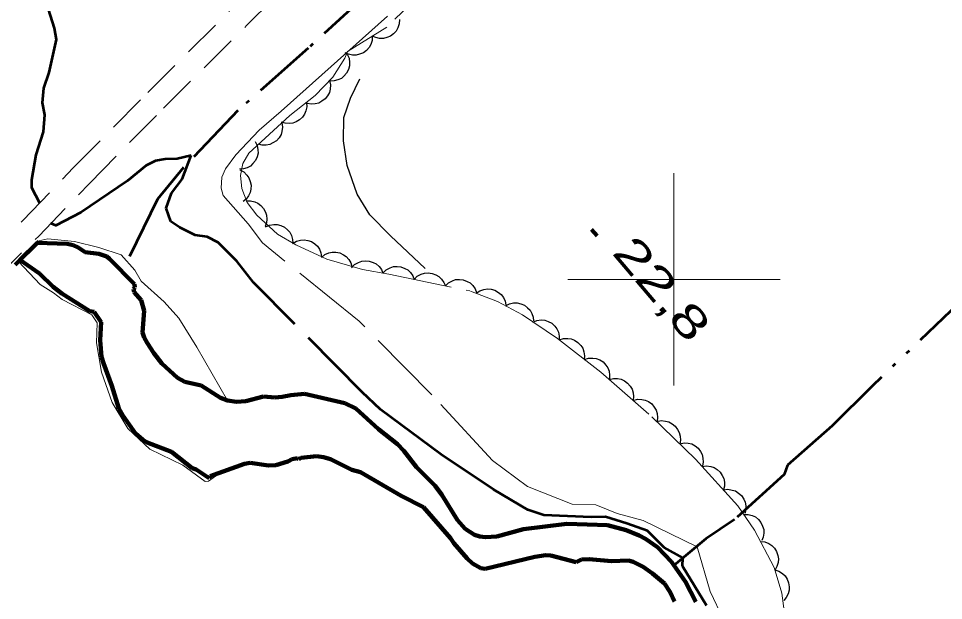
# Model space of a CAD drawing. Extents: x 386081 to 389416, y 5130568 to 5134082.
# Drawn here: x 387738.2 to 387825.4, y 5131569.7 to 5131624.6 of the extents above; entities that cross this region are included whole.
import ezdxf

# ---------------------------------------------------------------- set-up
doc = ezdxf.new("R2010")
doc.units = 0
doc.header["$LTSCALE"] = 1.2
for name, pattern in [('DASH_DOUBLE_DOT', [9.2, 5, -1.2, 0.3, -1.2, 0.3, -1.2]), ('DOT_DASHED', [7.7, 5, -1.2, 0.3, -1.2]), ('LONG_DASHED', [7.5, 6, -1.5]), ('MEDIUM_DASHED', [4.5, 3, -1.5])]:
    doc.linetypes.add(name, pattern=pattern)
for name, color, linetype, lineweight in [('1', 7, 'Continuous', 53), ('19', 7, 'Continuous', 13), ('2', 7, 'Continuous', 13), ('26', 7, 'Continuous', 35), ('3', 7, 'Continuous', 140), ('4', 7, 'DASH_DOUBLE_DOT', 53), ('41', 7, 'DOT_DASHED', 25), ('44', 7, 'Continuous', 25), ('61', 7, 'Continuous', 13)]:
    doc.layers.add(name, color=color, linetype=linetype, lineweight=lineweight)

msp = doc.modelspace()

# ---------------------------------------------------------------- linework, layer by layer
at = {"layer": '1'}
for points in [[(387740.24, 5131607.19), (387739.49, 5131608.63), (387739.51, 5131609.38), (387739.9, 5131611.73), (387740.59, 5131613.91), (387740.74, 5131615.51), (387740.52, 5131616.63), (387740.64, 5131618.01), (387741.13, 5131619.49), (387741.84, 5131622.62), (387741.65, 5131623.68), (387740.88, 5131626.05), (387740.11, 5131627.37), (387738.48, 5131629.5), (387737.41, 5131630.29), (387734.02, 5131631.07)], [(387748.52, 5131609.28), (387744.12, 5131606.29), (387741.76, 5131605.07), (387741.31, 5131605.26), (387741.3, 5131605.28)]]:
    msp.add_lwpolyline(points, dxfattribs=at)
at = {"layer": '1', "linetype": 'LONG_DASHED'}
msp.add_lwpolyline([(387803.06, 5131569.26), (387800.79, 5131572.99), (387800.84, 5131573.76), (387799.06, 5131574.75), (387797.5, 5131576.3), (387795.56, 5131577.01), (387793.54, 5131577.63), (387792.21, 5131577.59), (387787.73, 5131577.79), (387786.24, 5131578.28), (387782.99, 5131580.21), (387778.08, 5131583.51), (387772.34, 5131587.73), (387770.62, 5131589.38), (387760.37, 5131599.72), (387758.82, 5131601.73), (387757.06, 5131603.49), (387756.02, 5131604.01), (387754.89, 5131604.18), (387753.43, 5131604.9), (387752.6, 5131605.44), (387752.15, 5131606.71), (387752.65, 5131608.13), (387753.67, 5131609.46), (387754.51, 5131611.66), (387753.18, 5131611.36), (387752.07, 5131611.34), (387751.16, 5131611.18), (387750.28, 5131610.72), (387748.52, 5131609.28)], dxfattribs=at)
at = {"layer": '19', "linetype": 'MEDIUM_DASHED'}
for points in [[(387734.65, 5131601.63), (387738.66, 5131605.55), (387743.41, 5131610.5), (387750.42, 5131617.62), (387758.24, 5131625.4), (387776.47, 5131643.86), (387784.13, 5131650.96), (387789.84, 5131655.94), (387792.89, 5131658.2), (387799.26, 5131661.83), (387802.11, 5131663.66), (387806.2, 5131666.98), (387809.33, 5131670.03), (387818.67, 5131678.71), (387840.8, 5131699.08), (387852.77, 5131710.9), (387889.04, 5131745.94)], [(387735.96, 5131599.98), (387740.15, 5131604.08), (387744.92, 5131609.04), (387751.91, 5131616.13), (387759.73, 5131623.92), (387777.93, 5131642.34), (387785.53, 5131649.4), (387791.15, 5131654.3), (387794.03, 5131656.43), (387800.35, 5131660.04), (387803.34, 5131661.96), (387807.59, 5131665.41), (387810.78, 5131668.5), (387830.93, 5131687.19), (387842.49, 5131697.38), (387854.44, 5131709.18), (387890.7, 5131744.21)]]:
    msp.add_lwpolyline(points, dxfattribs=at)
at = {"layer": '2'}
for points in [[(387761.22, 5131603.43), (387759.89, 5131605.22), (387757.52, 5131607.91), (387757.33, 5131608.59), (387757.39, 5131609.62), (387757.74, 5131610.43), (387758.73, 5131611.74), (387760.92, 5131614.07), (387763, 5131615.84), (387773, 5131624.8)], [(387747.93, 5131602.32), (387745.81, 5131602.99), (387743.53, 5131603.58), (387741, 5131603.82), (387740.17, 5131603.62)], [(387738.25, 5131601.68), (387740.28, 5131599.51), (387741.54, 5131598.72), (387742.35, 5131598.09), (387745.16, 5131596.66), (387745.65, 5131595.92)]]:
    msp.add_lwpolyline(points, dxfattribs=at)
at = {"layer": '2', "linetype": 'LONG_DASHED'}
for points in [[(387806.05, 5131561.92), (387805.97, 5131564.2), (387804.63, 5131568.01), (387803.4, 5131570.59), (387802.18, 5131574.8), (387797.11, 5131577.28), (387794.65, 5131577.94), (387792.63, 5131578.76), (387790.42, 5131578.83), (387786.21, 5131580.49), (387782.91, 5131582.93), (387777.2, 5131589.12), (387770.34, 5131596.05), (387761.22, 5131603.43)], [(387757.95, 5131588.59), (387755.05, 5131593.61), (387753.34, 5131596.34), (387751.97, 5131597.9), (387749.81, 5131599.84), (387749.2, 5131600.86), (387747.93, 5131602.32)], [(387745.65, 5131595.92), (387745.59, 5131594.03), (387746.08, 5131591.26), (387747.07, 5131588.4), (387748.54, 5131585.94), (387750.61, 5131584.01), (387753.73, 5131582.49), (387755.83, 5131580.96), (387756.15, 5131580.98), (387757.11, 5131581.69)]]:
    msp.add_lwpolyline(points, dxfattribs=at)
at = {"layer": '26', "lineweight": 140}
msp.add_line((387737.92, 5131601.38), (387740.15, 5131603.58), dxfattribs=at)
at = {"layer": '3'}
msp.add_line((387792.24, 5131604.7), (387792.75, 5131604.09), dxfattribs=at)
at = {"layer": '4'}
for points in [[(388121.81, 5131885.17), (388061.37, 5131827.01), (388032.96, 5131799.48), (388009.57, 5131777.71), (387986.09, 5131755.15), (387957.98, 5131726.63), (387903.88, 5131672.92), (387851.5, 5131621.26), (387818.66, 5131589.95), (387814.9, 5131586.2), (387810.71, 5131582.48), (387810.39, 5131581.62), (387805.7, 5131577.36), (387803, 5131575.55), (387800, 5131573.05)], [(387899.3, 5131749.59), (387887.07, 5131737.5), (387872.02, 5131722.82), (387854.61, 5131706.42), (387846.32, 5131698.8), (387825.66, 5131678.92), (387810.45, 5131664.42), (387804.72, 5131659.09), (387802.21, 5131657.01), (387795.17, 5131651.78), (387791.12, 5131647.67), (387778.45, 5131634.05), (387771.45, 5131627.23), (387765.53, 5131621.78), (387758.91, 5131615.9), (387753.79, 5131610.54), (387751.35, 5131607.55), (387747.99, 5131600.76)]]:
    msp.add_lwpolyline(points, dxfattribs=at)
at = {"layer": '4', "linetype": 'LONG_DASHED', "lineweight": 90}
for points in [[(387800.04, 5131569.66), (387799.65, 5131570.53), (387799.1, 5131571.34), (387797.99, 5131572.3), (387797.09, 5131572.92), (387796.17, 5131573.38), (387795.7, 5131573.51), (387794.12, 5131573.45), (387792.01, 5131573.63), (387791.3, 5131573.59), (387790.77, 5131573.36), (387788.4, 5131573.98), (387787.92, 5131574), (387786.89, 5131573.86), (387782.21, 5131572.72), (387781.79, 5131572.79), (387781.02, 5131573.22), (387780.5, 5131573.71), (387779.27, 5131575.13), (387778.95, 5131575.63), (387776.39, 5131578.55), (387774.3, 5131579.59), (387770.46, 5131581.82), (387769.64, 5131582.05), (387767.64, 5131583.05), (387766.97, 5131583.26), (387766.33, 5131583.33), (387764.87, 5131583.18), (387764.66, 5131583.05), (387764.52, 5131583.15), (387764.02, 5131583.07), (387763.62, 5131582.83), (387762.49, 5131582.5), (387761.8, 5131582.45), (387760.07, 5131582.7), (387759.55, 5131582.61), (387756.3, 5131581.45), (387756.22, 5131581.28), (387754.99, 5131582.08), (387754.62, 5131582.21), (387752.65, 5131583.74), (387750.37, 5131584.63), (387749.96, 5131584.87), (387749.27, 5131585.49), (387748.08, 5131587.16), (387747.71, 5131587.82), (387747.03, 5131589.97), (387746.24, 5131592.09), (387746.06, 5131592.71), (387745.93, 5131594.28), (387746.02, 5131595.98), (387745.36, 5131596.94), (387744.97, 5131597.01), (387742.32, 5131598.68), (387741.51, 5131599.29), (387740.23, 5131600.55), (387738.37, 5131601.83), (387740.01, 5131603.44), (387742.83, 5131603.36), (387743.41, 5131603.22), (387743.87, 5131603.01), (387744.54, 5131602.57), (387745.82, 5131602.4), (387746.56, 5131602.16), (387746.82, 5131601.95), (387749.17, 5131599.54), (387749.21, 5131599.22), (387749.07, 5131599.08), (387749.13, 5131598.8), (387749.79, 5131598.04), (387750.1, 5131597.03), (387749.92, 5131595.01), (387750.09, 5131594.51), (387750.38, 5131594.01), (387750.98, 5131593.05), (387751.74, 5131592.07), (387753.22, 5131590.71), (387753.91, 5131590.34), (387755.45, 5131589.99), (387757.28, 5131588.84), (387757.95, 5131588.59), (387758.77, 5131588.47), (387759.65, 5131588.53), (387761.34, 5131588.96), (387762.38, 5131588.88), (387763.1, 5131588.92), (387763.91, 5131589.08), (387765.2, 5131589.2), (387768.99, 5131588.33), (387770.04, 5131587.84), (387772.17, 5131585.88)], [(387772.17, 5131585.88), (387773.96, 5131584.47), (387774.55, 5131583.84), (387775.73, 5131582.29), (387777.51, 5131580.55), (387778.14, 5131579.7), (387779.59, 5131577.32), (387780.34, 5131576.49), (387781.22, 5131575.92), (387781.71, 5131575.76), (387782.23, 5131575.71), (387783.32, 5131575.78), (387785.83, 5131576.46), (387789.9, 5131576.95), (387793.74, 5131576.84), (387795.48, 5131576.38), (387796.73, 5131575.87), (387797.33, 5131575.55), (387798.45, 5131574.76), (387799.76, 5131573.37), (387801.1, 5131571.51), (387802.06, 5131569.63)]]:
    msp.add_lwpolyline(points, dxfattribs=at)
at = {"layer": '41'}
msp.add_lwpolyline([(387776.56, 5131601.02), (387773.29, 5131604.1), (387771.35, 5131606.07), (387770.15, 5131608.04), (387769.21, 5131610.73), (387768.87, 5131613.06), (387768.9, 5131615.25), (387769.53, 5131617.08), (387770.41, 5131618.9)], dxfattribs=at)
at = {"layer": '44', "linetype": 'DOT_DASHED', "lineweight": 13}
msp.add_lwpolyline([(387784.62, 5131635.15), (387772.95, 5131623.77), (387769.23, 5131621.49), (387768.98, 5131620.84), (387767.85, 5131619.05), (387766.19, 5131617.33), (387763.8, 5131615.44), (387759.93, 5131611.9), (387759.37, 5131610.91), (387759.15, 5131609.78), (387759.28, 5131608.55), (387759.78, 5131607.26), (387760.69, 5131606.04), (387762.66, 5131604.26), (387764.36, 5131603.25), (387767.29, 5131601.92), (387770.66, 5131600.92), (387773.14, 5131600.5), (387780.82, 5131598.9), (387783.36, 5131597.92), (387785.72, 5131596.65), (387789.02, 5131594.42), (387793.1, 5131591.25), (387797.92, 5131587.05), (387802.04, 5131583.05), (387806.01, 5131578.67), (387807.6, 5131576.36), (387809.43, 5131572.84), (387810.15, 5131570.44), (387810.49, 5131568.05)], dxfattribs=at)
at = {"layer": '44'}
for points in [[(387774.14, 5131624.5), (387774.12, 5131624.08), (387773.98, 5131623.7), (387773.83, 5131623.4), (387773.59, 5131623.15), (387773.29, 5131622.93), (387772.94, 5131622.79), (387772.62, 5131622.7), (387772.27, 5131622.71), (387771.91, 5131622.78), (387771.58, 5131622.93)], [(387771.58, 5131622.93), (387771.56, 5131622.51), (387771.43, 5131622.13), (387771.28, 5131621.84), (387771.03, 5131621.58), (387770.74, 5131621.36), (387770.38, 5131621.22), (387770.07, 5131621.13), (387769.71, 5131621.14), (387769.35, 5131621.21), (387769.02, 5131621.36)], [(387769.22, 5131621.22), (387769.39, 5131620.84), (387769.44, 5131620.44), (387769.43, 5131620.11), (387769.33, 5131619.77), (387769.16, 5131619.44), (387768.9, 5131619.16), (387768.66, 5131618.94), (387768.34, 5131618.79), (387767.98, 5131618.7), (387767.62, 5131618.69)], [(387767.55, 5131618.74), (387767.64, 5131618.33), (387767.6, 5131617.93), (387767.53, 5131617.6), (387767.36, 5131617.3), (387767.13, 5131617.01), (387766.82, 5131616.78), (387766.54, 5131616.62), (387766.19, 5131616.54), (387765.82, 5131616.52), (387765.47, 5131616.58)], [(387765.37, 5131616.68), (387765.41, 5131616.27), (387765.32, 5131615.87), (387765.2, 5131615.56), (387764.99, 5131615.28), (387764.72, 5131615.03), (387764.39, 5131614.84), (387764.08, 5131614.72), (387763.73, 5131614.69), (387763.36, 5131614.72), (387763.02, 5131614.82)], [(387763.07, 5131614.77), (387763.13, 5131614.36), (387763.07, 5131613.95), (387762.98, 5131613.64), (387762.79, 5131613.34), (387762.54, 5131613.07), (387762.21, 5131612.86), (387761.92, 5131612.71), (387761.57, 5131612.66), (387761.2, 5131612.66), (387760.85, 5131612.74)], [(387760.55, 5131612.99), (387760.73, 5131612.62), (387760.8, 5131612.21), (387760.81, 5131611.88), (387760.72, 5131611.54), (387760.57, 5131611.21), (387760.33, 5131610.91), (387760.09, 5131610.68), (387759.78, 5131610.52), (387759.43, 5131610.41), (387759.07, 5131610.38)], [(387759.09, 5131610.32), (387759.46, 5131610.12), (387759.75, 5131609.83), (387759.95, 5131609.57), (387760.08, 5131609.24), (387760.15, 5131608.88), (387760.12, 5131608.5), (387760.07, 5131608.18), (387759.91, 5131607.86), (387759.68, 5131607.57), (387759.41, 5131607.33)], [(387759.68, 5131607.39), (387760.1, 5131607.41), (387760.5, 5131607.31), (387760.8, 5131607.18), (387761.08, 5131606.97), (387761.32, 5131606.69), (387761.5, 5131606.35), (387761.61, 5131606.04), (387761.64, 5131605.69), (387761.6, 5131605.32), (387761.48, 5131604.98)], [(387761.51, 5131604.94), (387761.89, 5131605.12), (387762.29, 5131605.18), (387762.62, 5131605.18), (387762.96, 5131605.09), (387763.29, 5131604.93), (387763.58, 5131604.68), (387763.81, 5131604.44), (387763.96, 5131604.13), (387764.07, 5131603.77), (387764.09, 5131603.41)], [(387764.07, 5131603.38), (387764.43, 5131603.6), (387764.82, 5131603.7), (387765.15, 5131603.74), (387765.5, 5131603.68), (387765.85, 5131603.56), (387766.16, 5131603.35), (387766.41, 5131603.14), (387766.6, 5131602.84), (387766.74, 5131602.5), (387766.8, 5131602.14)], [(387766.78, 5131602.07), (387767.1, 5131602.34), (387767.48, 5131602.49), (387767.8, 5131602.58), (387768.15, 5131602.57), (387768.51, 5131602.49), (387768.85, 5131602.32), (387769.13, 5131602.15), (387769.36, 5131601.88), (387769.55, 5131601.56), (387769.66, 5131601.22)], [(387769.63, 5131601.1), (387769.91, 5131601.4), (387770.27, 5131601.6), (387770.58, 5131601.72), (387770.93, 5131601.75), (387771.29, 5131601.72), (387771.66, 5131601.6), (387771.95, 5131601.46), (387772.21, 5131601.22), (387772.43, 5131600.92), (387772.58, 5131600.59)], [(387772.59, 5131600.61), (387772.89, 5131600.91), (387773.25, 5131601.09), (387773.56, 5131601.2), (387773.91, 5131601.22), (387774.28, 5131601.18), (387774.64, 5131601.04), (387774.93, 5131600.89), (387775.17, 5131600.64), (387775.39, 5131600.34), (387775.53, 5131600)], [(387775.53, 5131600), (387775.82, 5131600.29), (387776.19, 5131600.48), (387776.5, 5131600.59), (387776.85, 5131600.61), (387777.22, 5131600.57), (387777.57, 5131600.43), (387777.86, 5131600.28), (387778.11, 5131600.03), (387778.33, 5131599.72), (387778.46, 5131599.39)], [(387778.46, 5131599.39), (387778.76, 5131599.68), (387779.12, 5131599.87), (387779.43, 5131599.98), (387779.79, 5131600), (387780.15, 5131599.95), (387780.51, 5131599.81), (387780.8, 5131599.66), (387781.05, 5131599.41), (387781.26, 5131599.11), (387781.4, 5131598.78)], [(387781.37, 5131598.69), (387781.71, 5131598.93), (387782.1, 5131599.05), (387782.43, 5131599.11), (387782.78, 5131599.07), (387783.13, 5131598.97), (387783.46, 5131598.77), (387783.72, 5131598.58), (387783.93, 5131598.29), (387784.09, 5131597.96), (387784.17, 5131597.61)], [(387784.13, 5131597.51), (387784.5, 5131597.7), (387784.89, 5131597.78), (387785.22, 5131597.8), (387785.57, 5131597.71), (387785.91, 5131597.57), (387786.21, 5131597.33), (387786.44, 5131597.11), (387786.61, 5131596.8), (387786.73, 5131596.44), (387786.77, 5131596.09)], [(387786.71, 5131595.98), (387787.09, 5131596.14), (387787.5, 5131596.18), (387787.83, 5131596.16), (387788.16, 5131596.04), (387788.48, 5131595.86), (387788.76, 5131595.6), (387788.97, 5131595.35), (387789.11, 5131595.03), (387789.19, 5131594.66), (387789.19, 5131594.3)], [(387789.18, 5131594.29), (387789.58, 5131594.42), (387789.99, 5131594.43), (387790.31, 5131594.39), (387790.64, 5131594.26), (387790.95, 5131594.06), (387791.21, 5131593.77), (387791.4, 5131593.51), (387791.51, 5131593.18), (387791.58, 5131592.81), (387791.55, 5131592.45)], [(387791.55, 5131592.45), (387791.95, 5131592.58), (387792.36, 5131592.59), (387792.68, 5131592.55), (387793.01, 5131592.42), (387793.32, 5131592.22), (387793.58, 5131591.93), (387793.77, 5131591.67), (387793.88, 5131591.34), (387793.94, 5131590.97), (387793.92, 5131590.61)], [(387793.88, 5131590.57), (387794.29, 5131590.67), (387794.69, 5131590.66), (387795.02, 5131590.6), (387795.33, 5131590.45), (387795.63, 5131590.23), (387795.88, 5131589.93), (387796.06, 5131589.66), (387796.15, 5131589.32), (387796.19, 5131588.95), (387796.15, 5131588.6)], [(387796.15, 5131588.6), (387796.55, 5131588.7), (387796.96, 5131588.69), (387797.28, 5131588.63), (387797.6, 5131588.48), (387797.9, 5131588.26), (387798.14, 5131587.96), (387798.32, 5131587.69), (387798.41, 5131587.35), (387798.45, 5131586.98), (387798.41, 5131586.63)], [(387798.38, 5131586.6), (387798.79, 5131586.69), (387799.2, 5131586.65), (387799.52, 5131586.58), (387799.83, 5131586.4), (387800.11, 5131586.17), (387800.34, 5131585.86), (387800.5, 5131585.58), (387800.58, 5131585.23), (387800.6, 5131584.86), (387800.54, 5131584.51)], [(387800.54, 5131584.51), (387800.95, 5131584.6), (387801.35, 5131584.56), (387801.67, 5131584.49), (387801.98, 5131584.31), (387802.27, 5131584.08), (387802.49, 5131583.77), (387802.66, 5131583.49), (387802.73, 5131583.15), (387802.75, 5131582.77), (387802.69, 5131582.42)], [(387802.65, 5131582.38), (387803.06, 5131582.44), (387803.46, 5131582.38), (387803.78, 5131582.28), (387804.07, 5131582.09), (387804.35, 5131581.84), (387804.55, 5131581.52), (387804.7, 5131581.23), (387804.75, 5131580.88), (387804.75, 5131580.51), (387804.66, 5131580.16)], [(387804.66, 5131580.16), (387805.08, 5131580.22), (387805.48, 5131580.15), (387805.79, 5131580.06), (387806.09, 5131579.87), (387806.36, 5131579.62), (387806.57, 5131579.3), (387806.71, 5131579), (387806.77, 5131578.66), (387806.76, 5131578.28), (387806.68, 5131577.93)], [(387806.57, 5131577.85), (387806.99, 5131577.86), (387807.38, 5131577.74), (387807.68, 5131577.61), (387807.95, 5131577.38), (387808.18, 5131577.09), (387808.35, 5131576.74), (387808.45, 5131576.44), (387808.46, 5131576.08), (387808.4, 5131575.72), (387808.27, 5131575.38)], [(387808.15, 5131575.31), (387808.56, 5131575.26), (387808.94, 5131575.1), (387809.22, 5131574.92), (387809.46, 5131574.66), (387809.65, 5131574.35), (387809.77, 5131573.99), (387809.84, 5131573.67), (387809.8, 5131573.32), (387809.7, 5131572.96), (387809.53, 5131572.64)], [(387809.49, 5131572.63), (387809.89, 5131572.5), (387810.23, 5131572.27), (387810.47, 5131572.05), (387810.66, 5131571.75), (387810.79, 5131571.41), (387810.84, 5131571.03), (387810.85, 5131570.7), (387810.75, 5131570.37), (387810.58, 5131570.03), (387810.36, 5131569.75)]]:
    msp.add_lwpolyline(points, dxfattribs=at)
at = {"layer": '61'}
for p, q in [((387800, 5131590), (387800, 5131610)), ((387790, 5131600), (387810, 5131600))]:
    msp.add_line(p, q, dxfattribs=at)

# ---------------------------------------------------------------- texts
at = {"layer": '3', "width": 1.45}
msp.add_text('22,8   ', height=3, rotation=310.294, dxfattribs=at).set_placement((387794.07, 5131602.48))

doc.saveas('drawing.dxf')
